(* Logix 5000 project; controller Test vendor 1 type 14 code 92 rev 33.11; software revision 33.00; part 3 of 3 *)
(* tags used below, declared in another part *)
   K50Z : Banner_K50Z_v4;
   Port_Data : Banner_IOL_Port_v4;
   Port : DINT;
   Local_Control : DINT;
   Command_Being_Processed : BOOL;
   Update_Archive : BOOL;
   Index_Write_Inprocess : INT;
   Inprocess_Index : DINT;
(* Banner_K50Z_Param_v4, continued *)

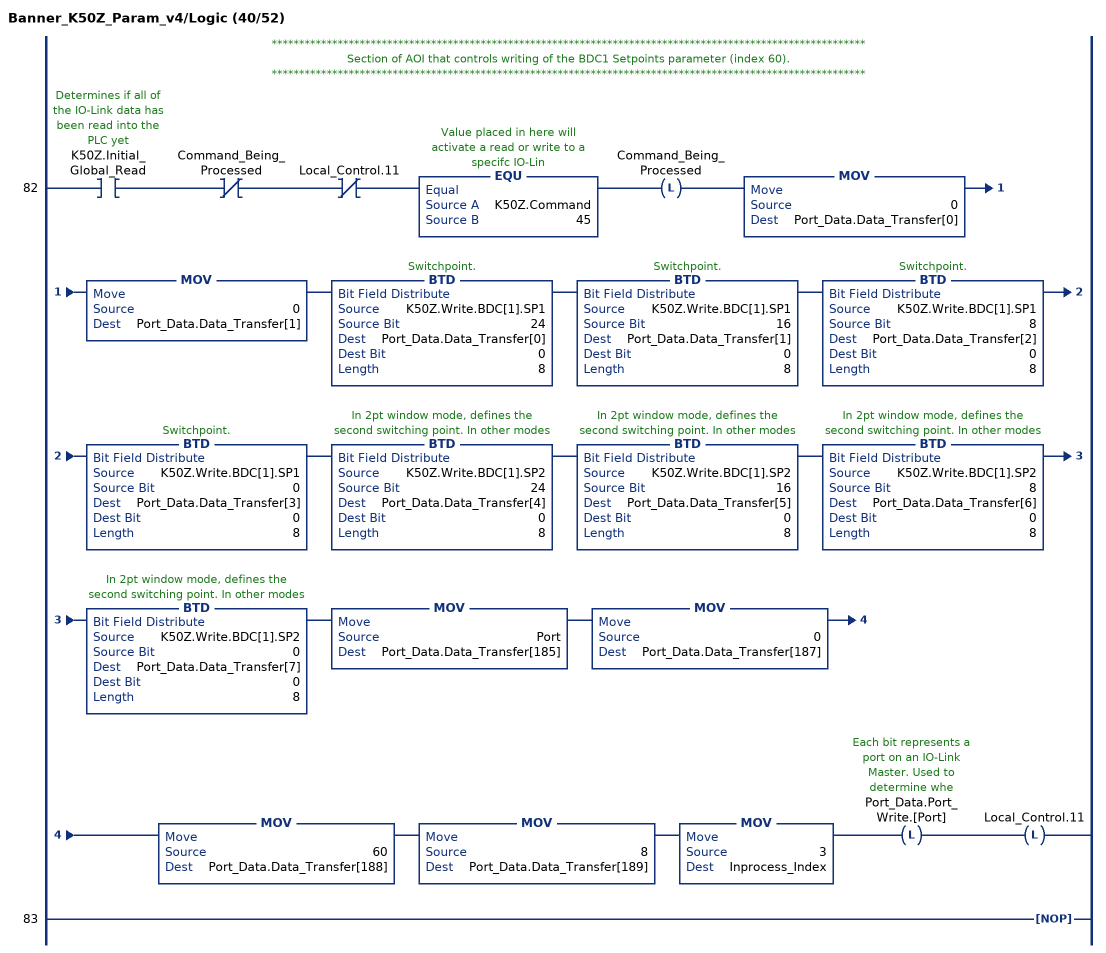
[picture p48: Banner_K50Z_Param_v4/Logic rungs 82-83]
   // ************************************************************************************************************
   // Section of AOI that controls writing of the BDC1 Setpoints parameter (index 60).
   // ************************************************************************************************************
   82: XIC(K50Z.Initial_Global_Read)XIO(Command_Being_Processed)XIO(Local_Control.11)EQU(K50Z.Command,45)OTL(Command_Being_Processed)MOV(0,Port_Data.Data_Transfer[0])MOV(0,Port_Data.Data_Transfer[1])BTD(K50Z.Write.BDC[1].SP1,24,Port_Data.Data_Transfer[0],0,8)BTD(K50Z.Write.BDC[1].SP1,16,Port_Data.Data_Transfer[1],0,8)BTD(K50Z.Write.BDC[1].SP1,8,Port_Data.Data_Transfer[2],0,8)BTD(K50Z.Write.BDC[1].SP1,0,Port_Data.Data_Transfer[3],0,8)BTD(K50Z.Write.BDC[1].SP2,24,Port_Data.Data_Transfer[4],0,8)BTD(K50Z.Write.BDC[1].SP2,16,Port_Data.Data_Transfer[5],0,8)BTD(K50Z.Write.BDC[1].SP2,8,Port_Data.Data_Transfer[6],0,8)BTD(K50Z.Write.BDC[1].SP2,0,Port_Data.Data_Transfer[7],0,8)MOV(Port,Port_Data.Data_Transfer[185])MOV(0,Port_Data.Data_Transfer[187])MOV(60,Port_Data.Data_Transfer[188])MOV(8,Port_Data.Data_Transfer[189])MOV(3,Inprocess_Index)OTL(Port_Data.Port_Write.[Port])OTL(Local_Control.11);
   83: NOP();
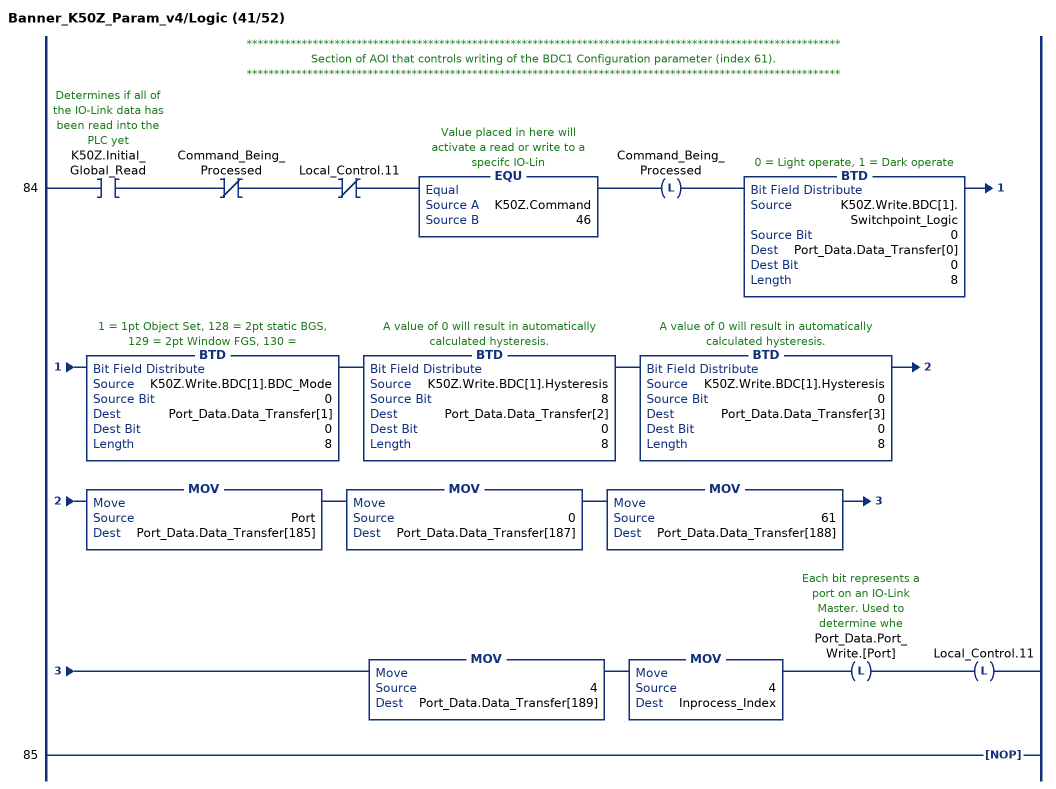
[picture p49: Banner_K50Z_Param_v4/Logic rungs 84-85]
   // ************************************************************************************************************
   // Section of AOI that controls writing of the BDC1 Configuration parameter (index 61).
   // ************************************************************************************************************
   84: XIC(K50Z.Initial_Global_Read)XIO(Command_Being_Processed)XIO(Local_Control.11)EQU(K50Z.Command,46)OTL(Command_Being_Processed)BTD(K50Z.Write.BDC[1].Switchpoint_Logic,0,Port_Data.Data_Transfer[0],0,8)BTD(K50Z.Write.BDC[1].BDC_Mode,0,Port_Data.Data_Transfer[1],0,8)BTD(K50Z.Write.BDC[1].Hysteresis,8,Port_Data.Data_Transfer[2],0,8)BTD(K50Z.Write.BDC[1].Hysteresis,0,Port_Data.Data_Transfer[3],0,8)MOV(Port,Port_Data.Data_Transfer[185])MOV(0,Port_Data.Data_Transfer[187])MOV(61,Port_Data.Data_Transfer[188])MOV(4,Port_Data.Data_Transfer[189])MOV(4,Inprocess_Index)OTL(Port_Data.Port_Write.[Port])OTL(Local_Control.11);
   85: NOP();
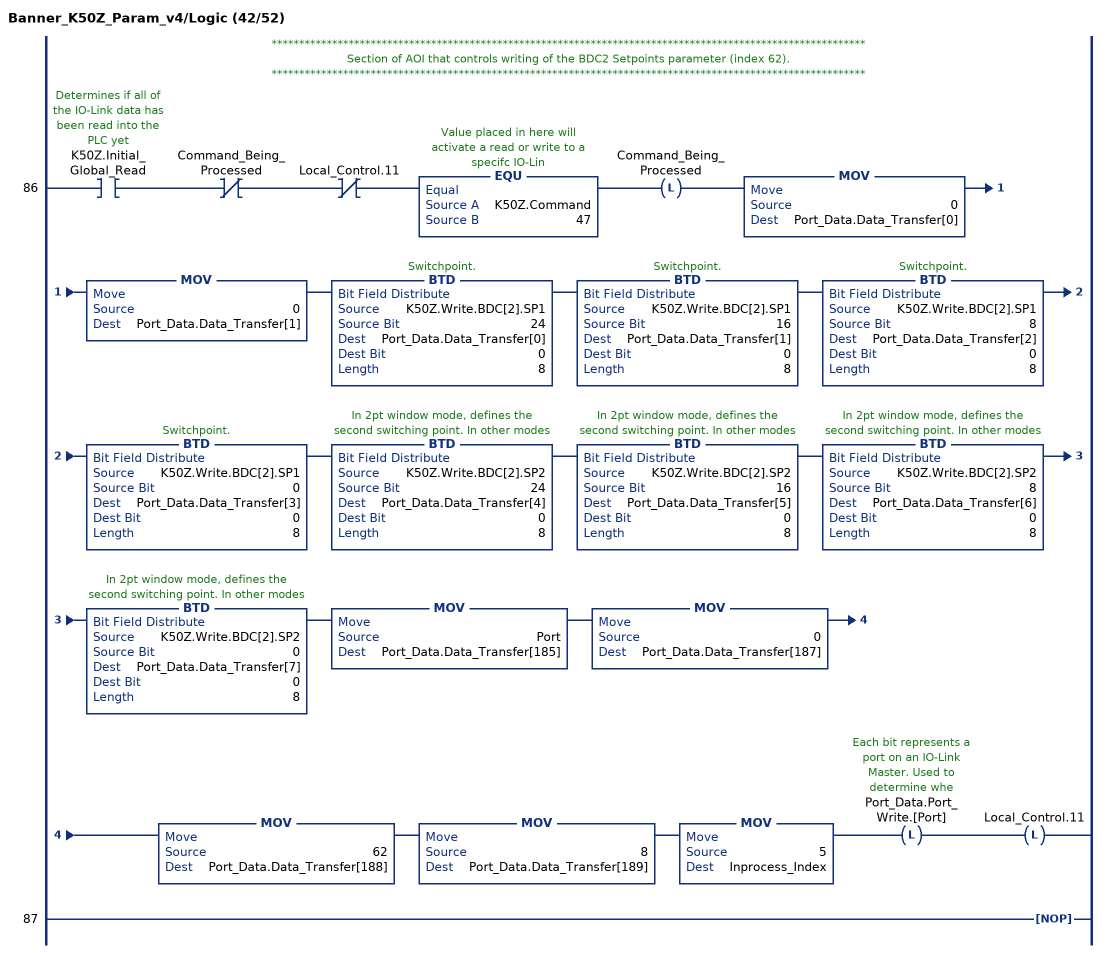
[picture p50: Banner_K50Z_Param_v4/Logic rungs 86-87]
   // ************************************************************************************************************
   // Section of AOI that controls writing of the BDC2 Setpoints parameter (index 62).
   // ************************************************************************************************************
   86: XIC(K50Z.Initial_Global_Read)XIO(Command_Being_Processed)XIO(Local_Control.11)EQU(K50Z.Command,47)OTL(Command_Being_Processed)MOV(0,Port_Data.Data_Transfer[0])MOV(0,Port_Data.Data_Transfer[1])BTD(K50Z.Write.BDC[2].SP1,24,Port_Data.Data_Transfer[0],0,8)BTD(K50Z.Write.BDC[2].SP1,16,Port_Data.Data_Transfer[1],0,8)BTD(K50Z.Write.BDC[2].SP1,8,Port_Data.Data_Transfer[2],0,8)BTD(K50Z.Write.BDC[2].SP1,0,Port_Data.Data_Transfer[3],0,8)BTD(K50Z.Write.BDC[2].SP2,24,Port_Data.Data_Transfer[4],0,8)BTD(K50Z.Write.BDC[2].SP2,16,Port_Data.Data_Transfer[5],0,8)BTD(K50Z.Write.BDC[2].SP2,8,Port_Data.Data_Transfer[6],0,8)BTD(K50Z.Write.BDC[2].SP2,0,Port_Data.Data_Transfer[7],0,8)MOV(Port,Port_Data.Data_Transfer[185])MOV(0,Port_Data.Data_Transfer[187])MOV(62,Port_Data.Data_Transfer[188])MOV(8,Port_Data.Data_Transfer[189])MOV(5,Inprocess_Index)OTL(Port_Data.Port_Write.[Port])OTL(Local_Control.11);
   87: NOP();
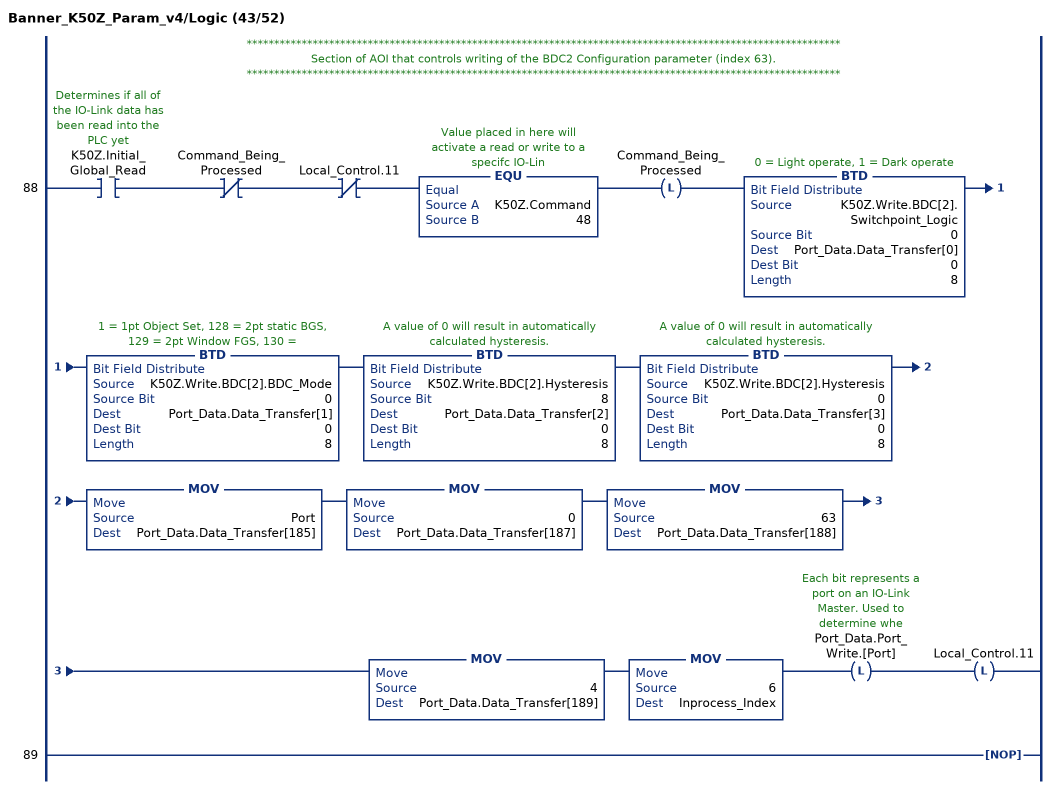
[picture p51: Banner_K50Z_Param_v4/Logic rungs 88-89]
   // ************************************************************************************************************
   // Section of AOI that controls writing of the BDC2 Configuration parameter (index 63).
   // ************************************************************************************************************
   88: XIC(K50Z.Initial_Global_Read)XIO(Command_Being_Processed)XIO(Local_Control.11)EQU(K50Z.Command,48)OTL(Command_Being_Processed)BTD(K50Z.Write.BDC[2].Switchpoint_Logic,0,Port_Data.Data_Transfer[0],0,8)BTD(K50Z.Write.BDC[2].BDC_Mode,0,Port_Data.Data_Transfer[1],0,8)BTD(K50Z.Write.BDC[2].Hysteresis,8,Port_Data.Data_Transfer[2],0,8)BTD(K50Z.Write.BDC[2].Hysteresis,0,Port_Data.Data_Transfer[3],0,8)MOV(Port,Port_Data.Data_Transfer[185])MOV(0,Port_Data.Data_Transfer[187])MOV(63,Port_Data.Data_Transfer[188])MOV(4,Port_Data.Data_Transfer[189])MOV(6,Inprocess_Index)OTL(Port_Data.Port_Write.[Port])OTL(Local_Control.11);
   89: NOP();
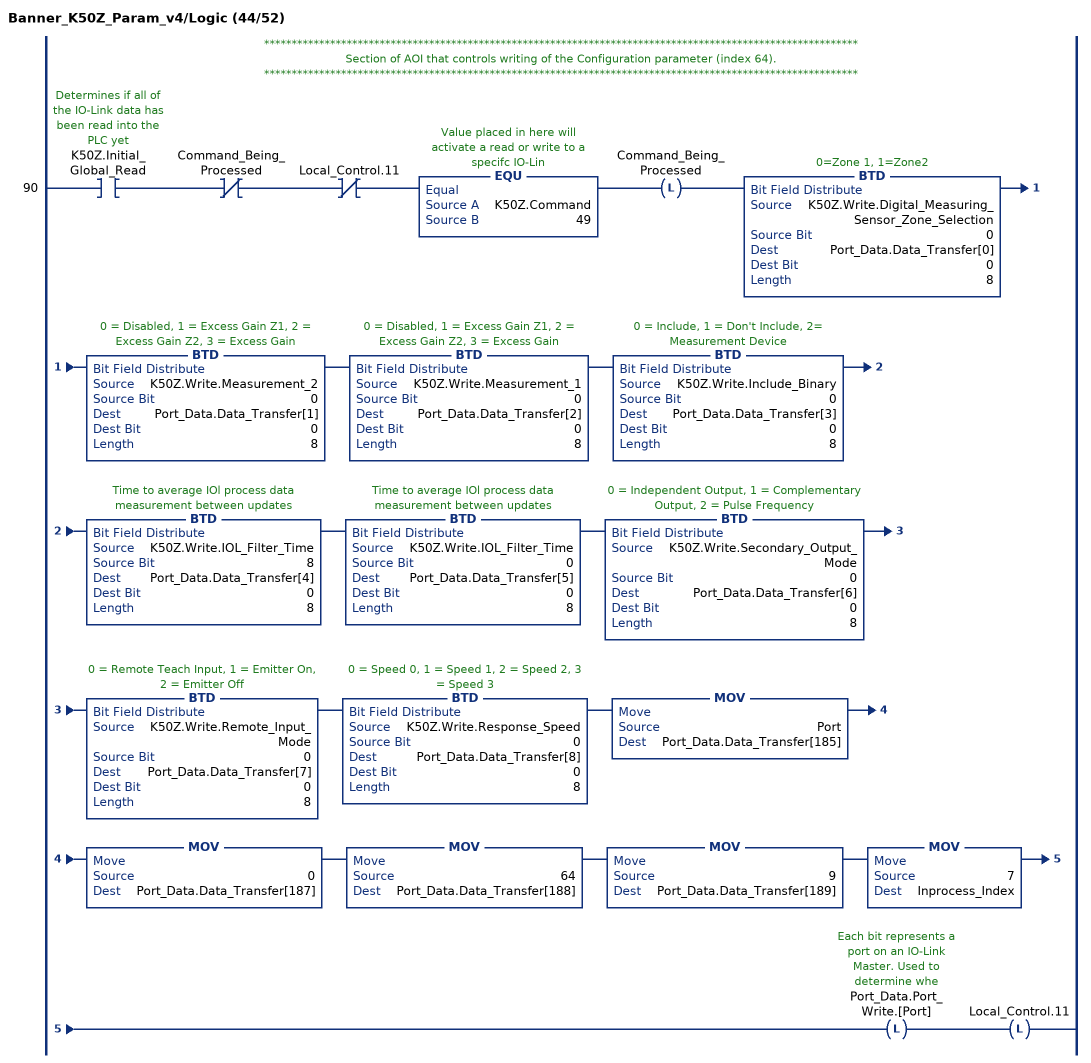
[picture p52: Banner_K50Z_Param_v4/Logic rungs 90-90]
   // ************************************************************************************************************
   // Section of AOI that controls writing of the Configuration parameter (index 64).
   // ************************************************************************************************************
   90: XIC(K50Z.Initial_Global_Read)XIO(Command_Being_Processed)XIO(Local_Control.11)EQU(K50Z.Command,49)OTL(Command_Being_Processed)BTD(K50Z.Write.Digital_Measuring_Sensor_Zone_Selection,0,Port_Data.Data_Transfer[0],0,8)BTD(K50Z.Write.Measurement_2,0,Port_Data.Data_Transfer[1],0,8)BTD(K50Z.Write.Measurement_1,0,Port_Data.Data_Transfer[2],0,8)BTD(K50Z.Write.Include_Binary,0,Port_Data.Data_Transfer[3],0,8)BTD(K50Z.Write.IOL_Filter_Time,8,Port_Data.Data_Transfer[4],0,8)BTD(K50Z.Write.IOL_Filter_Time,0,Port_Data.Data_Transfer[5],0,8)BTD(K50Z.Write.Secondary_Output_Mode,0,Port_Data.Data_Transfer[6],0,8)BTD(K50Z.Write.Remote_Input_Mode,0,Port_Data.Data_Transfer[7],0,8)BTD(K50Z.Write.Response_Speed,0,Port_Data.Data_Transfer[8],0,8)MOV(Port,Port_Data.Data_Transfer[185])MOV(0,Port_Data.Data_Transfer[187])MOV(64,Port_Data.Data_Transfer[188])MOV(9,Port_Data.Data_Transfer[189])MOV(7,Inprocess_Index)OTL(Port_Data.Port_Write.[Port])OTL(Local_Control.11);
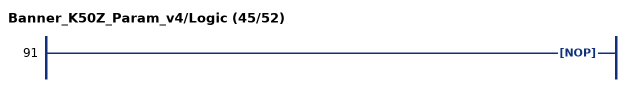
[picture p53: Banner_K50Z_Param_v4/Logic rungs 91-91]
   91: NOP();
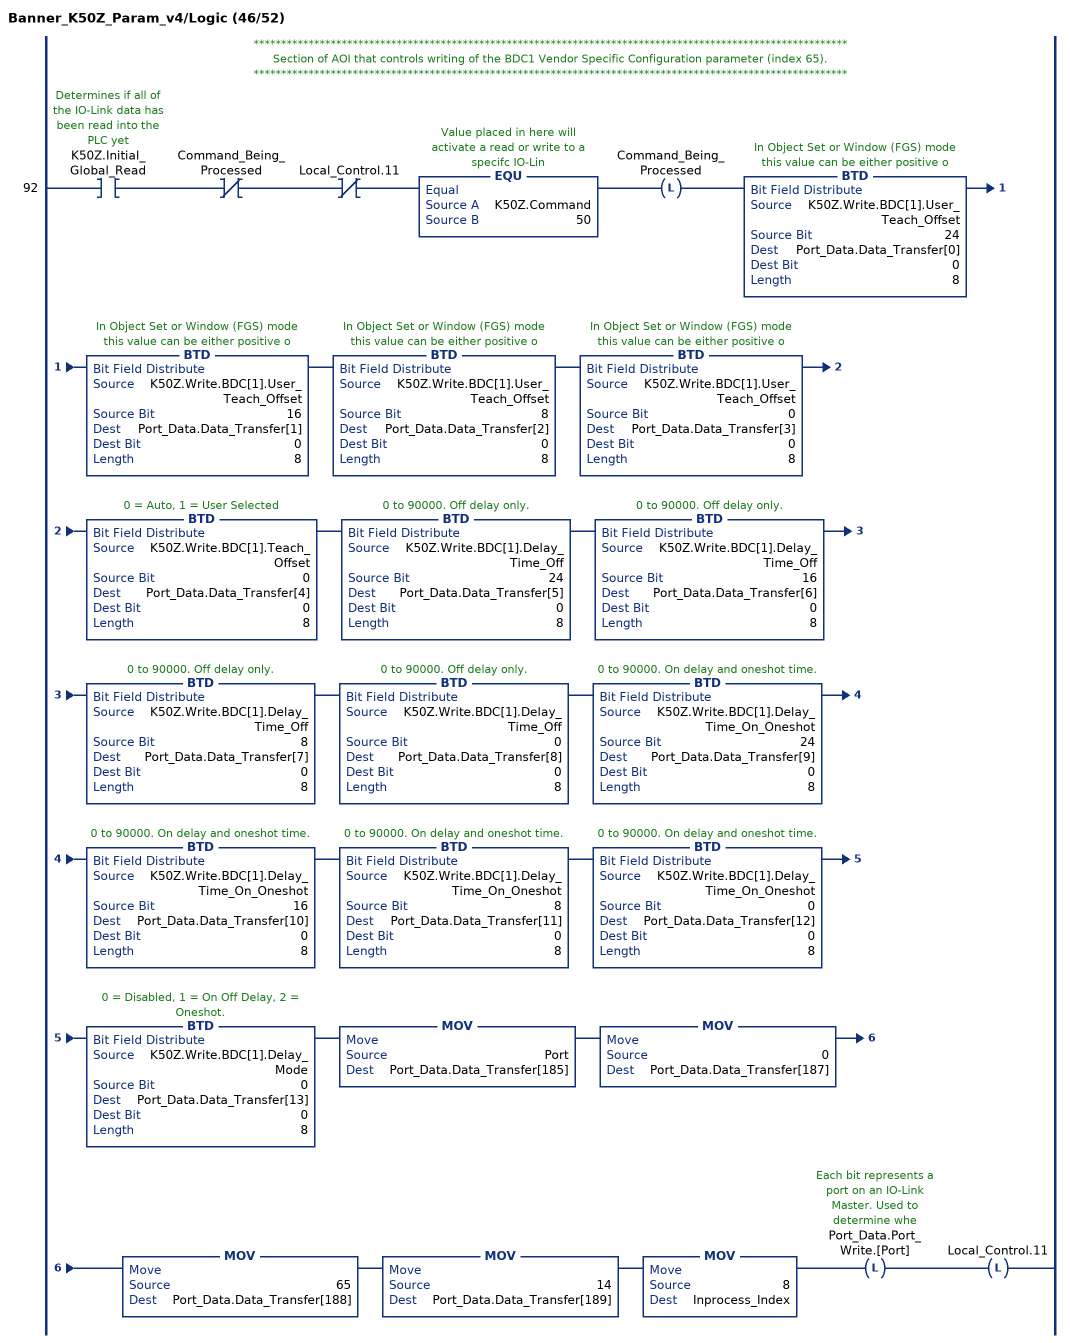
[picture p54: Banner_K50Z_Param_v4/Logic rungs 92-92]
   // ************************************************************************************************************
   // Section of AOI that controls writing of the BDC1 Vendor Specific Configuration parameter (index 65).
   // ************************************************************************************************************
   92: XIC(K50Z.Initial_Global_Read)XIO(Command_Being_Processed)XIO(Local_Control.11)EQU(K50Z.Command,50)OTL(Command_Being_Processed)BTD(K50Z.Write.BDC[1].User_Teach_Offset,24,Port_Data.Data_Transfer[0],0,8)BTD(K50Z.Write.BDC[1].User_Teach_Offset,16,Port_Data.Data_Transfer[1],0,8)BTD(K50Z.Write.BDC[1].User_Teach_Offset,8,Port_Data.Data_Transfer[2],0,8)BTD(K50Z.Write.BDC[1].User_Teach_Offset,0,Port_Data.Data_Transfer[3],0,8)BTD(K50Z.Write.BDC[1].Teach_Offset,0,Port_Data.Data_Transfer[4],0,8)BTD(K50Z.Write.BDC[1].Delay_Time_Off,24,Port_Data.Data_Transfer[5],0,8)BTD(K50Z.Write.BDC[1].Delay_Time_Off,16,Port_Data.Data_Transfer[6],0,8)BTD(K50Z.Write.BDC[1].Delay_Time_Off,8,Port_Data.Data_Transfer[7],0,8)BTD(K50Z.Write.BDC[1].Delay_Time_Off,0,Port_Data.Data_Transfer[8],0,8)BTD(K50Z.Write.BDC[1].Delay_Time_On_Oneshot,24,Port_Data.Data_Transfer[9],0,8)BTD(K50Z.Write.BDC[1].Delay_Time_On_Oneshot,16,Port_Data.Data_Transfer[10],0,8)BTD(K50Z.Write.BDC[1].Delay_Time_On_Oneshot,8,Port_Data.Data_Transfer[11],0,8)BTD(K50Z.Write.BDC[1].Delay_Time_On_Oneshot,0,Port_Data.Data_Transfer[12],0,8)BTD(K50Z.Write.BDC[1].Delay_Mode,0,Port_Data.Data_Transfer[13],0,8)MOV(Port,Port_Data.Data_Transfer[185])MOV(0,Port_Data.Data_Transfer[187])MOV(65,Port_Data.Data_Transfer[188])MOV(14,Port_Data.Data_Transfer[189])MOV(8,Inprocess_Index)OTL(Port_Data.Port_Write.[Port])OTL(Local_Control.11);
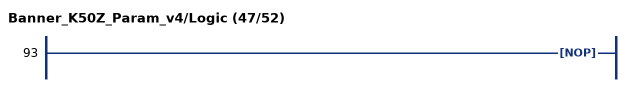
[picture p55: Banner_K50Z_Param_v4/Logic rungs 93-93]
   93: NOP();
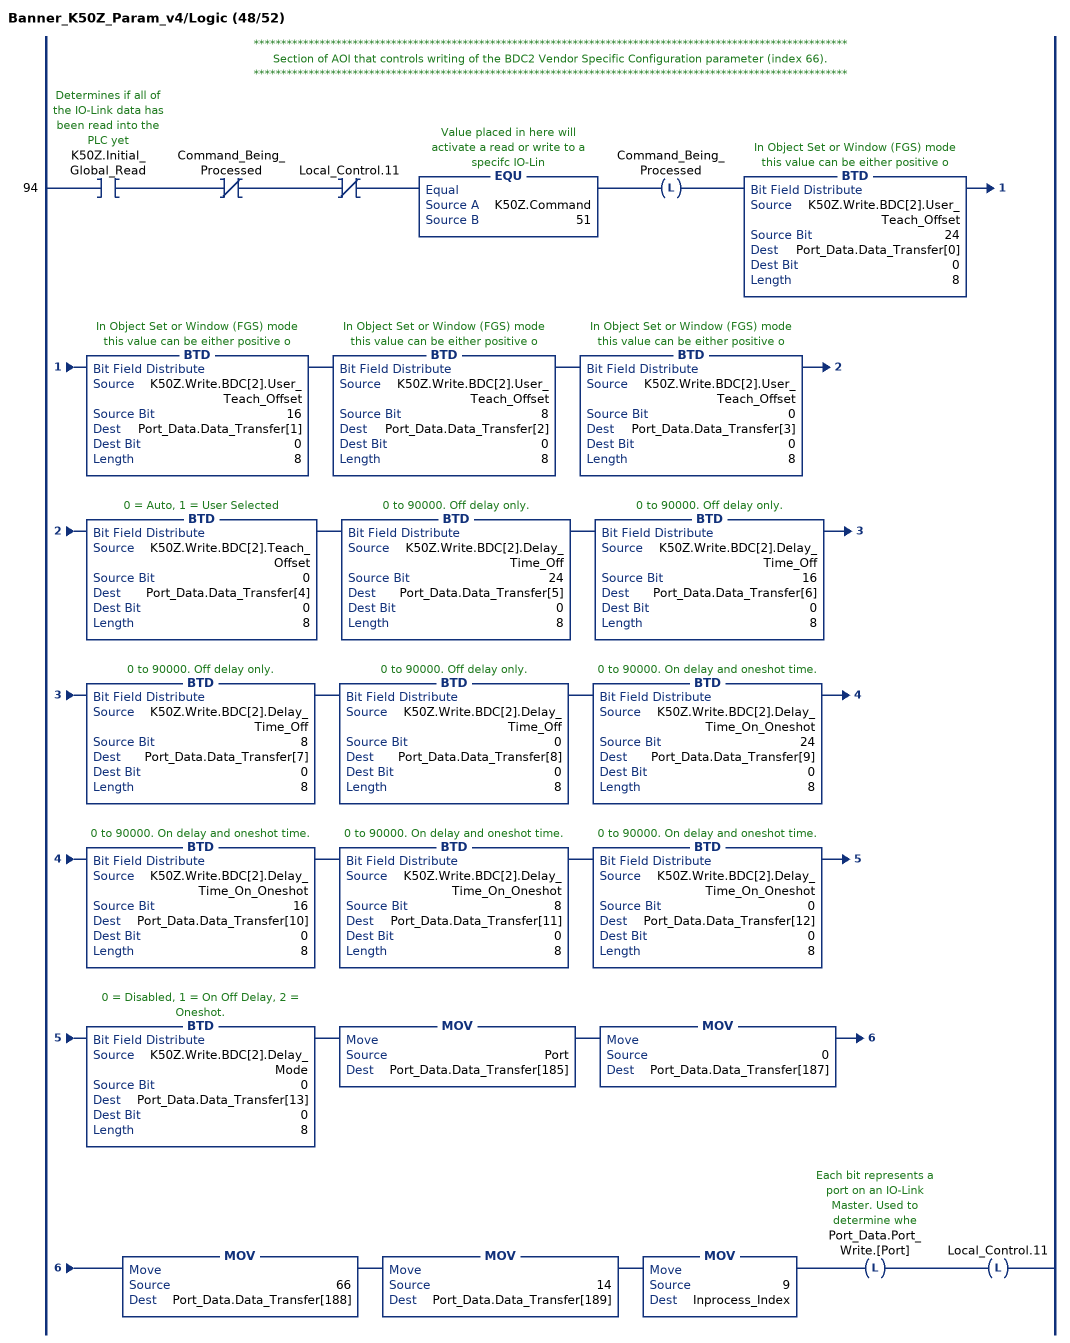
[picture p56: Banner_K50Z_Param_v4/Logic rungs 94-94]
   // ************************************************************************************************************
   // Section of AOI that controls writing of the BDC2 Vendor Specific Configuration parameter (index 66).
   // ************************************************************************************************************
   94: XIC(K50Z.Initial_Global_Read)XIO(Command_Being_Processed)XIO(Local_Control.11)EQU(K50Z.Command,51)OTL(Command_Being_Processed)BTD(K50Z.Write.BDC[2].User_Teach_Offset,24,Port_Data.Data_Transfer[0],0,8)BTD(K50Z.Write.BDC[2].User_Teach_Offset,16,Port_Data.Data_Transfer[1],0,8)BTD(K50Z.Write.BDC[2].User_Teach_Offset,8,Port_Data.Data_Transfer[2],0,8)BTD(K50Z.Write.BDC[2].User_Teach_Offset,0,Port_Data.Data_Transfer[3],0,8)BTD(K50Z.Write.BDC[2].Teach_Offset,0,Port_Data.Data_Transfer[4],0,8)BTD(K50Z.Write.BDC[2].Delay_Time_Off,24,Port_Data.Data_Transfer[5],0,8)BTD(K50Z.Write.BDC[2].Delay_Time_Off,16,Port_Data.Data_Transfer[6],0,8)BTD(K50Z.Write.BDC[2].Delay_Time_Off,8,Port_Data.Data_Transfer[7],0,8)BTD(K50Z.Write.BDC[2].Delay_Time_Off,0,Port_Data.Data_Transfer[8],0,8)BTD(K50Z.Write.BDC[2].Delay_Time_On_Oneshot,24,Port_Data.Data_Transfer[9],0,8)BTD(K50Z.Write.BDC[2].Delay_Time_On_Oneshot,16,Port_Data.Data_Transfer[10],0,8)BTD(K50Z.Write.BDC[2].Delay_Time_On_Oneshot,8,Port_Data.Data_Transfer[11],0,8)BTD(K50Z.Write.BDC[2].Delay_Time_On_Oneshot,0,Port_Data.Data_Transfer[12],0,8)BTD(K50Z.Write.BDC[2].Delay_Mode,0,Port_Data.Data_Transfer[13],0,8)MOV(Port,Port_Data.Data_Transfer[185])MOV(0,Port_Data.Data_Transfer[187])MOV(66,Port_Data.Data_Transfer[188])MOV(14,Port_Data.Data_Transfer[189])MOV(9,Inprocess_Index)OTL(Port_Data.Port_Write.[Port])OTL(Local_Control.11);
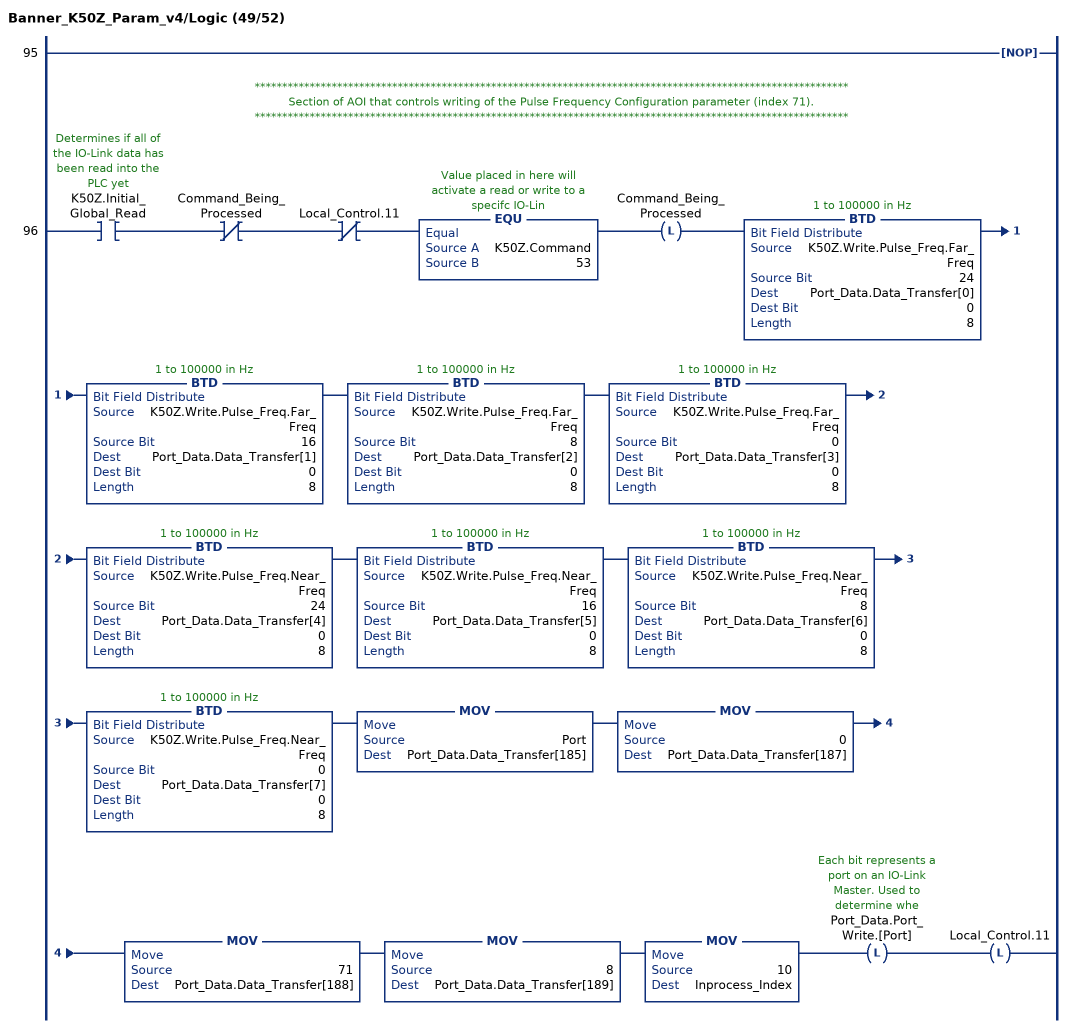
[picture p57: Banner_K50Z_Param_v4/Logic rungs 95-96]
   95: NOP();
   // ************************************************************************************************************
   // Section of AOI that controls writing of the Pulse Frequency Configuration parameter (index 71).
   // ************************************************************************************************************
   96: XIC(K50Z.Initial_Global_Read)XIO(Command_Being_Processed)XIO(Local_Control.11)EQU(K50Z.Command,53)OTL(Command_Being_Processed)BTD(K50Z.Write.Pulse_Freq.Far_Freq,24,Port_Data.Data_Transfer[0],0,8)BTD(K50Z.Write.Pulse_Freq.Far_Freq,16,Port_Data.Data_Transfer[1],0,8)BTD(K50Z.Write.Pulse_Freq.Far_Freq,8,Port_Data.Data_Transfer[2],0,8)BTD(K50Z.Write.Pulse_Freq.Far_Freq,0,Port_Data.Data_Transfer[3],0,8)BTD(K50Z.Write.Pulse_Freq.Near_Freq,24,Port_Data.Data_Transfer[4],0,8)BTD(K50Z.Write.Pulse_Freq.Near_Freq,16,Port_Data.Data_Transfer[5],0,8)BTD(K50Z.Write.Pulse_Freq.Near_Freq,8,Port_Data.Data_Transfer[6],0,8)BTD(K50Z.Write.Pulse_Freq.Near_Freq,0,Port_Data.Data_Transfer[7],0,8)MOV(Port,Port_Data.Data_Transfer[185])MOV(0,Port_Data.Data_Transfer[187])MOV(71,Port_Data.Data_Transfer[188])MOV(8,Port_Data.Data_Transfer[189])MOV(10,Inprocess_Index)OTL(Port_Data.Port_Write.[Port])OTL(Local_Control.11);
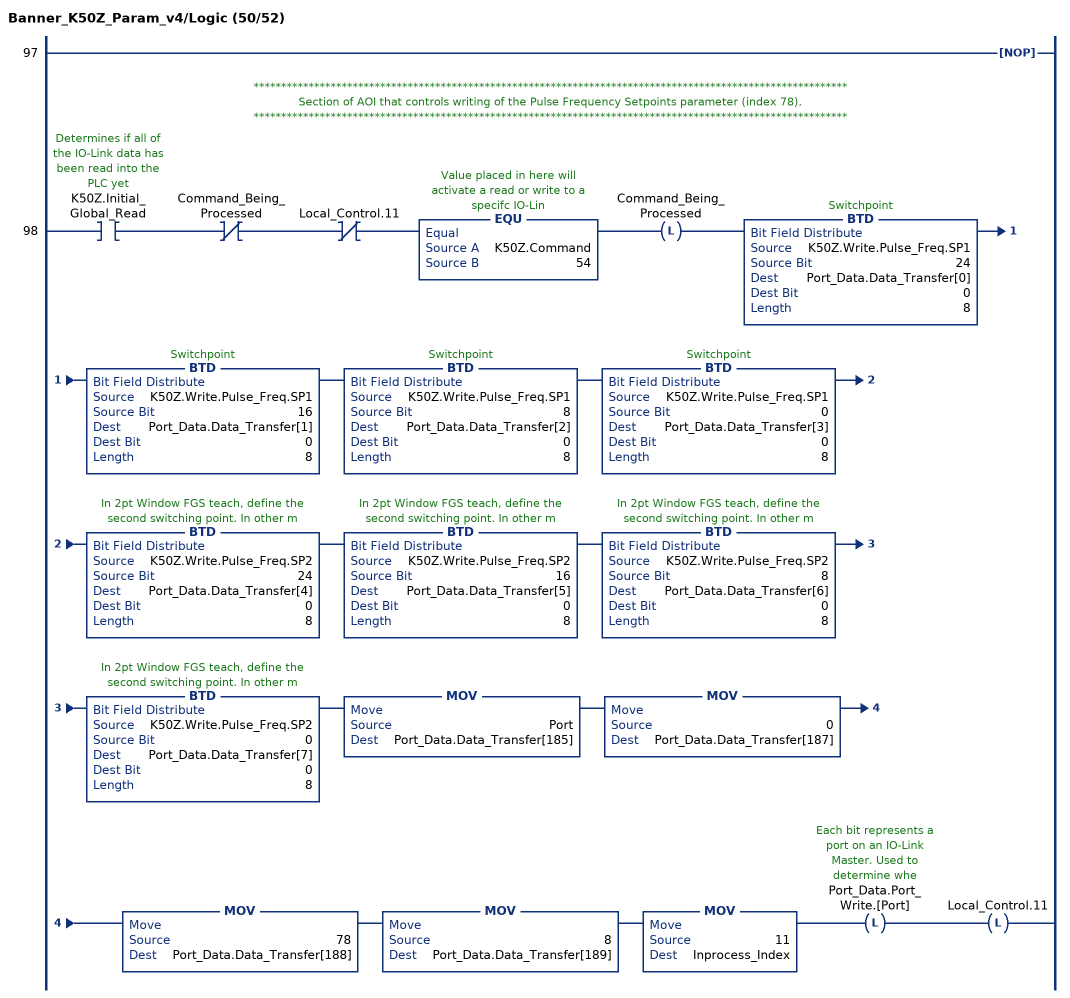
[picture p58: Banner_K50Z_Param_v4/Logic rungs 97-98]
   97: NOP();
   // ************************************************************************************************************
   // Section of AOI that controls writing of the Pulse Frequency Setpoints parameter (index 78).
   // ************************************************************************************************************
   98: XIC(K50Z.Initial_Global_Read)XIO(Command_Being_Processed)XIO(Local_Control.11)EQU(K50Z.Command,54)OTL(Command_Being_Processed)BTD(K50Z.Write.Pulse_Freq.SP1,24,Port_Data.Data_Transfer[0],0,8)BTD(K50Z.Write.Pulse_Freq.SP1,16,Port_Data.Data_Transfer[1],0,8)BTD(K50Z.Write.Pulse_Freq.SP1,8,Port_Data.Data_Transfer[2],0,8)BTD(K50Z.Write.Pulse_Freq.SP1,0,Port_Data.Data_Transfer[3],0,8)BTD(K50Z.Write.Pulse_Freq.SP2,24,Port_Data.Data_Transfer[4],0,8)BTD(K50Z.Write.Pulse_Freq.SP2,16,Port_Data.Data_Transfer[5],0,8)BTD(K50Z.Write.Pulse_Freq.SP2,8,Port_Data.Data_Transfer[6],0,8)BTD(K50Z.Write.Pulse_Freq.SP2,0,Port_Data.Data_Transfer[7],0,8)MOV(Port,Port_Data.Data_Transfer[185])MOV(0,Port_Data.Data_Transfer[187])MOV(78,Port_Data.Data_Transfer[188])MOV(8,Port_Data.Data_Transfer[189])MOV(11,Inprocess_Index)OTL(Port_Data.Port_Write.[Port])OTL(Local_Control.11);
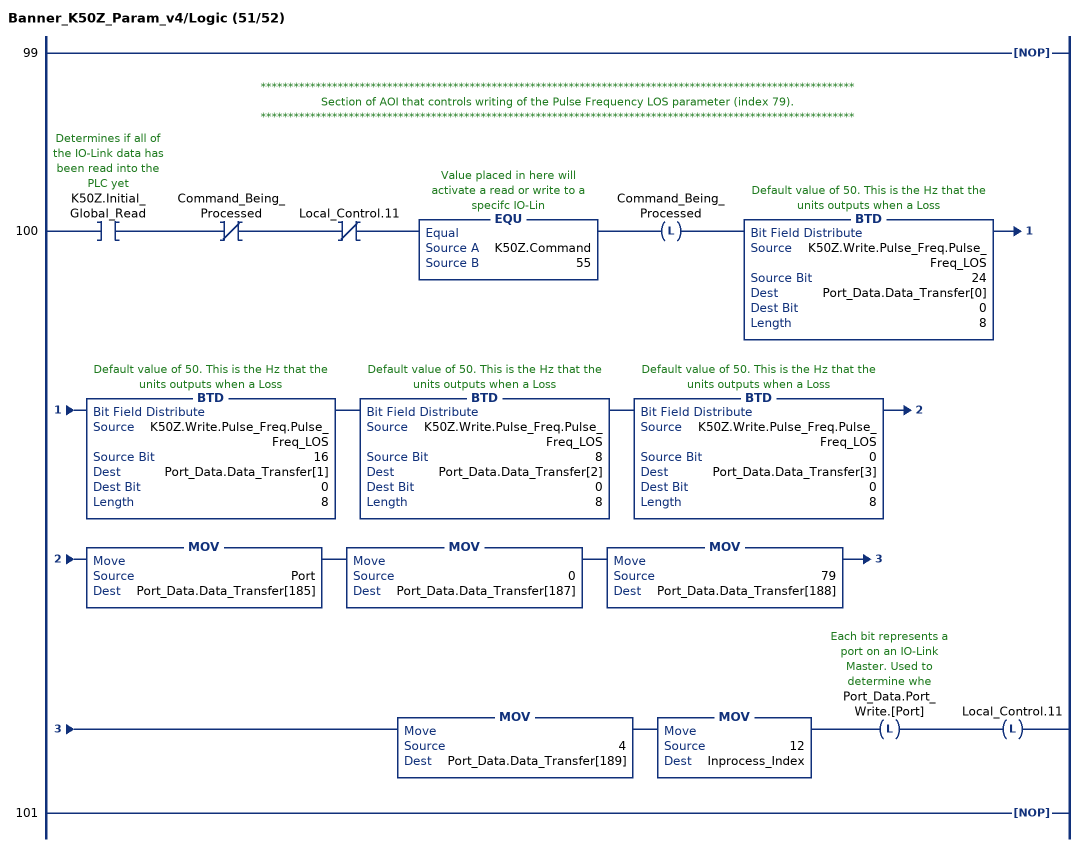
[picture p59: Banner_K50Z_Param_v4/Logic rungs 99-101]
   99: NOP();
   // ************************************************************************************************************
   // Section of AOI that controls writing of the Pulse Frequency LOS parameter (index 79).
   // ************************************************************************************************************
   100: XIC(K50Z.Initial_Global_Read)XIO(Command_Being_Processed)XIO(Local_Control.11)EQU(K50Z.Command,55)OTL(Command_Being_Processed)BTD(K50Z.Write.Pulse_Freq.Pulse_Freq_LOS,24,Port_Data.Data_Transfer[0],0,8)BTD(K50Z.Write.Pulse_Freq.Pulse_Freq_LOS,16,Port_Data.Data_Transfer[1],0,8)BTD(K50Z.Write.Pulse_Freq.Pulse_Freq_LOS,8,Port_Data.Data_Transfer[2],0,8)BTD(K50Z.Write.Pulse_Freq.Pulse_Freq_LOS,0,Port_Data.Data_Transfer[3],0,8)MOV(Port,Port_Data.Data_Transfer[185])MOV(0,Port_Data.Data_Transfer[187])MOV(79,Port_Data.Data_Transfer[188])MOV(4,Port_Data.Data_Transfer[189])MOV(12,Inprocess_Index)OTL(Port_Data.Port_Write.[Port])OTL(Local_Control.11);
   101: NOP();
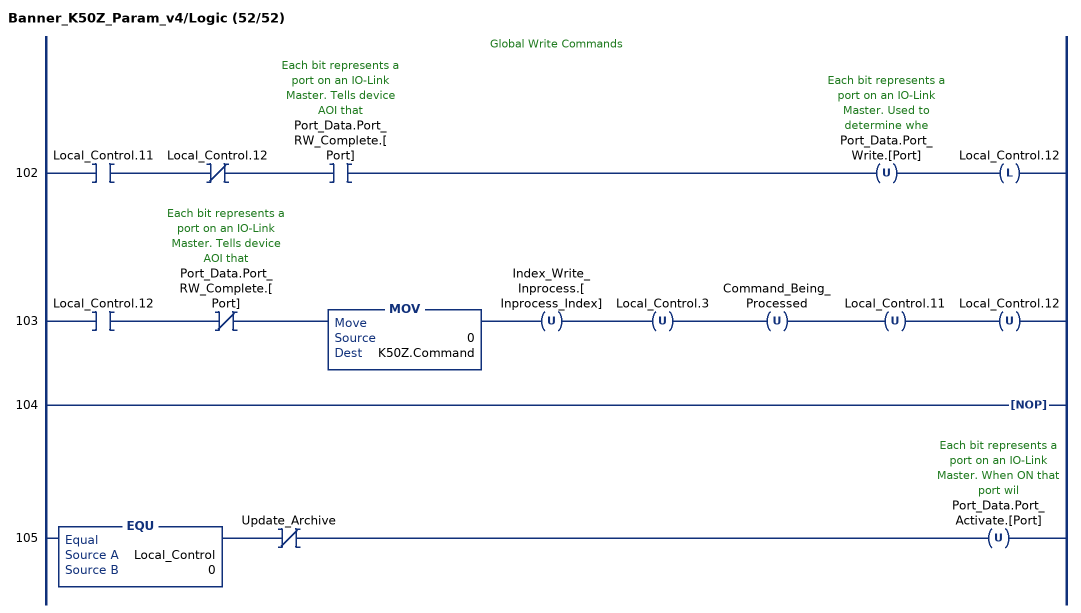
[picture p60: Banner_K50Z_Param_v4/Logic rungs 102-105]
   // Global Write Commands
   102: XIC(Local_Control.11)XIO(Local_Control.12)XIC(Port_Data.Port_RW_Complete.[Port])OTU(Port_Data.Port_Write.[Port])OTL(Local_Control.12);
   103: XIC(Local_Control.12)XIO(Port_Data.Port_RW_Complete.[Port])MOV(0,K50Z.Command)OTU(Index_Write_Inprocess.[Inprocess_Index])OTU(Local_Control.3)OTU(Command_Being_Processed)OTU(Local_Control.11)OTU(Local_Control.12);
   104: NOP();
   105: EQU(Local_Control,0)XIO(Update_Archive)OTU(Port_Data.Port_Activate.[Port]);
END_ROUTINE
END_ADD_ON_INSTRUCTION

ADD_ON_INSTRUCTION Banner_K50Z_PD_v4   (* revision 4.1, vendor Banner Engineering *)
// Take raw process data and convert it to usable values.
VAR_IN_OUT
   PD : Banner_K50Z_PDIO_v4; {required}   // Process Data for a Q5X.
END_VAR
VAR_INPUT
   Configuration : SINT; {required}
   Byte_Swap : BOOL; {required}
END_VAR
VAR
   TempI : SINT[4]; {access None}
END_VAR

ROUTINE Logic   (* ladder *)
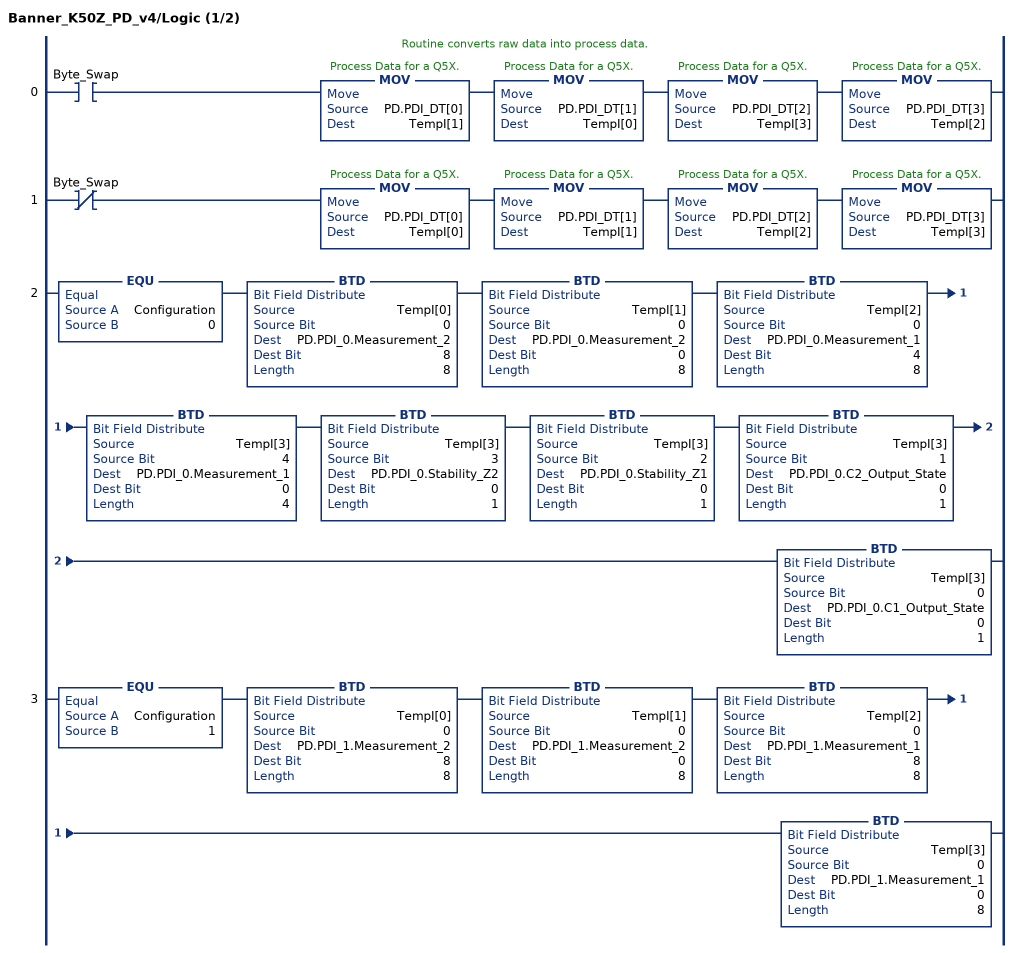
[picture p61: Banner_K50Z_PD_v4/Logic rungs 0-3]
   // Routine converts raw data into process data.
   0: XIC(Byte_Swap)MOV(PD.PDI_DT[0],TempI[1])MOV(PD.PDI_DT[1],TempI[0])MOV(PD.PDI_DT[2],TempI[3])MOV(PD.PDI_DT[3],TempI[2]);
   1: XIO(Byte_Swap)MOV(PD.PDI_DT[0],TempI[0])MOV(PD.PDI_DT[1],TempI[1])MOV(PD.PDI_DT[2],TempI[2])MOV(PD.PDI_DT[3],TempI[3]);
   2: EQU(Configuration,0)BTD(TempI[0],0,PD.PDI_0.Measurement_2,8,8)BTD(TempI[1],0,PD.PDI_0.Measurement_2,0,8)BTD(TempI[2],0,PD.PDI_0.Measurement_1,4,8)BTD(TempI[3],4,PD.PDI_0.Measurement_1,0,4)BTD(TempI[3],3,PD.PDI_0.Stability_Z2,0,1)BTD(TempI[3],2,PD.PDI_0.Stability_Z1,0,1)BTD(TempI[3],1,PD.PDI_0.C2_Output_State,0,1)BTD(TempI[3],0,PD.PDI_0.C1_Output_State,0,1);
   3: EQU(Configuration,1)BTD(TempI[0],0,PD.PDI_1.Measurement_2,8,8)BTD(TempI[1],0,PD.PDI_1.Measurement_2,0,8)BTD(TempI[2],0,PD.PDI_1.Measurement_1,8,8)BTD(TempI[3],0,PD.PDI_1.Measurement_1,0,8);
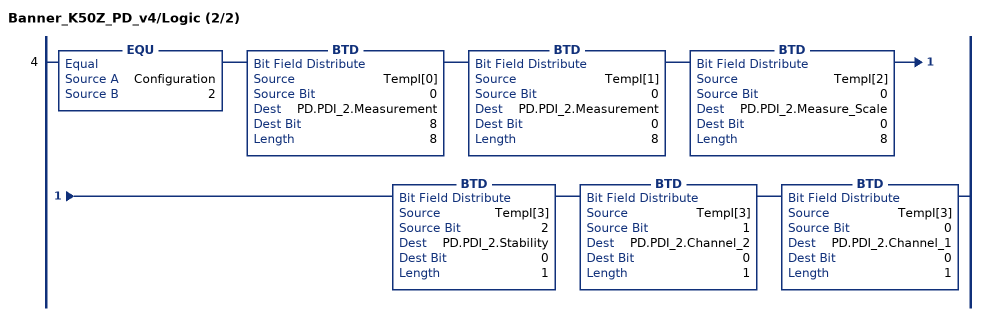
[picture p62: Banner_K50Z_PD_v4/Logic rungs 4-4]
   4: EQU(Configuration,2)BTD(TempI[0],0,PD.PDI_2.Measurement,8,8)BTD(TempI[1],0,PD.PDI_2.Measurement,0,8)BTD(TempI[2],0,PD.PDI_2.Measure_Scale,0,8)BTD(TempI[3],2,PD.PDI_2.Stability,0,1)BTD(TempI[3],1,PD.PDI_2.Channel_2,0,1)BTD(TempI[3],0,PD.PDI_2.Channel_1,0,1);
END_ROUTINE
END_ADD_ON_INSTRUCTION

VAR_GLOBAL   (* controller tags *)
   IOLM1 : Banner_IOLM_v4;
   IOLM1_Status : Banner_DXMR90_IOLM_v4;
   K50Z_IOLM1_01 : Banner_K50Z_v4;
   K50Z_IOLM1_01_PD : Banner_K50Z_PDIO_v4 := (PDI_0.C2_Output_State := 1, PDI_0.Stability_Z1 := 1, PDI_0.Stability_Z2 := 1, PDI_0.Measurement_1 := 692, PDI_0.Measurement_2 := 576, PDI_1.Measurement_1 := 250, PDI_1.Measurement_2 := 2000);
   K50Z_IOLM1_01_PD_Status : Banner_K50Z_PD_v4;
   K50Z_IOLM1_01_Status : Banner_K50Z_Param_v4;
   Manual_Reset : BOOL;
END_VAR

PROGRAM MainProgram   (* main routine MainRoutine *)

ROUTINE MainRoutine   (* ladder *)
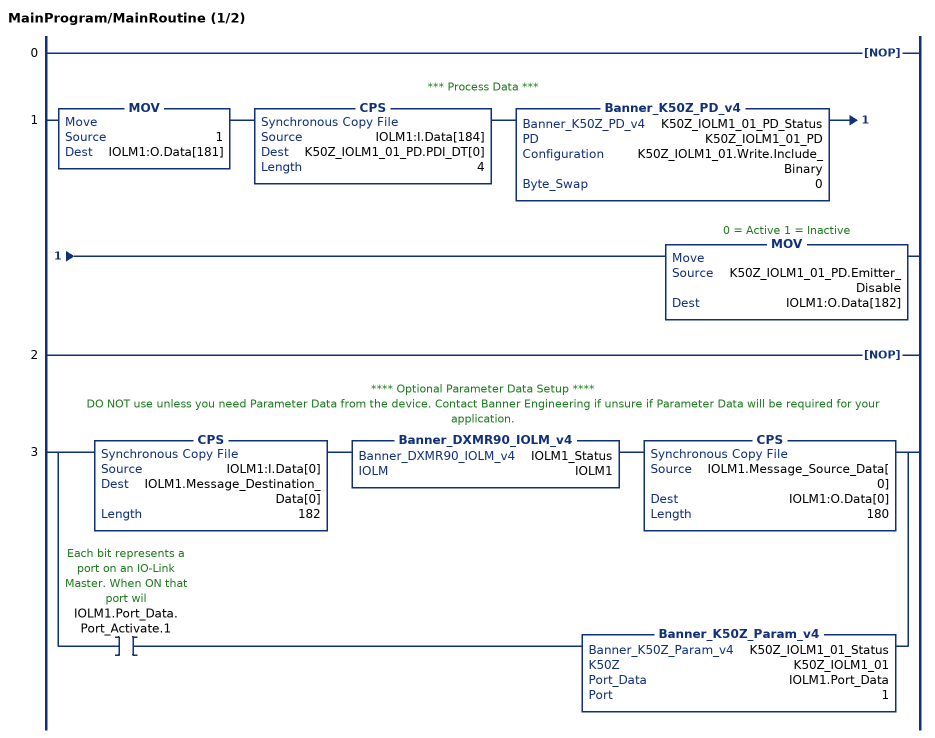
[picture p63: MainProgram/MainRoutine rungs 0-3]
   0: NOP();
   // *** Process Data ***
   1: MOV(1,IOLM1:O.Data[181])CPS(IOLM1:I.Data[184],K50Z_IOLM1_01_PD.PDI_DT[0],4)Banner_K50Z_PD_v4(K50Z_IOLM1_01_PD_Status,K50Z_IOLM1_01_PD,K50Z_IOLM1_01.Write.Include_Binary,0)MOV(K50Z_IOLM1_01_PD.Emitter_Disable,IOLM1:O.Data[182]);
   2: NOP();
   // **** Optional Parameter Data Setup ****
   // DO NOT use unless you need Parameter Data from the device. Contact Banner Engineering if unsure if Parameter Data will be required for your application.
   3: [CPS(IOLM1:I.Data[0],IOLM1.Message_Destination_Data[0],182) Banner_DXMR90_IOLM_v4(IOLM1_Status,IOLM1) CPS(IOLM1.Message_Source_Data[0],IOLM1:O.Data[0],180) ,XIC(IOLM1.Port_Data.Port_Activate.1) Banner_K50Z_Param_v4(K50Z_IOLM1_01_Status,K50Z_IOLM1_01,IOLM1.Port_Data,1) ];
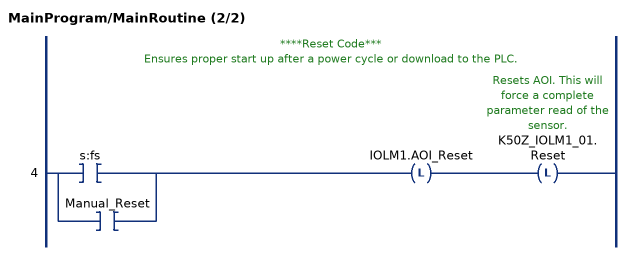
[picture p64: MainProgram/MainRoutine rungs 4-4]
   // ****Reset Code***
   // Ensures proper start up after a power cycle or download to the PLC.
   4: [XIC(s:fs) ,XIC(Manual_Reset) ]OTL(IOLM1.AOI_Reset)OTL(K50Z_IOLM1_01.Reset);
END_ROUTINE
END_PROGRAM
